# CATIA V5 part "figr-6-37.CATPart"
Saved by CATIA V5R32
Part number: Part1
Bounding box of the stored display mesh (mm): x -36 to 36, y -75 to 75, z -15.252 to 15.252
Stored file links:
  D:\PROJECTS\Project 2022\CATIA V5 6R 2022\Resources\Part Files\c06_catia_v5_6r2022_prt\figr-6-37.CATPart
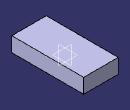
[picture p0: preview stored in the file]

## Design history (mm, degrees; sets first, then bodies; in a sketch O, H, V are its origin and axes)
Body1 (main body)
  Sketch1 on yz-plane, origin (0, 0, 0), H (0, 1, 0), V (0, 0, 1)
    line L1 (-75, 15.2515) -> (75, 15.2515)
    line L2 (75, 15.2515) -> (75, -15.2515)
    line L3 (75, -15.2515) -> (-75, -15.2515)
    line L4 (-75, -15.2515) -> (-75, 15.2515)
    axis line L5 (75, -15.2515) -> (-75, 15.2515)
    length L1 = 150
    horizontal: L1 H, L3 H
    vertical: L2 V, L4 V
    midpoint: O L5
  Pad1: profile Sketch1, direction (1, 0, 0), length 36, mirrored extent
